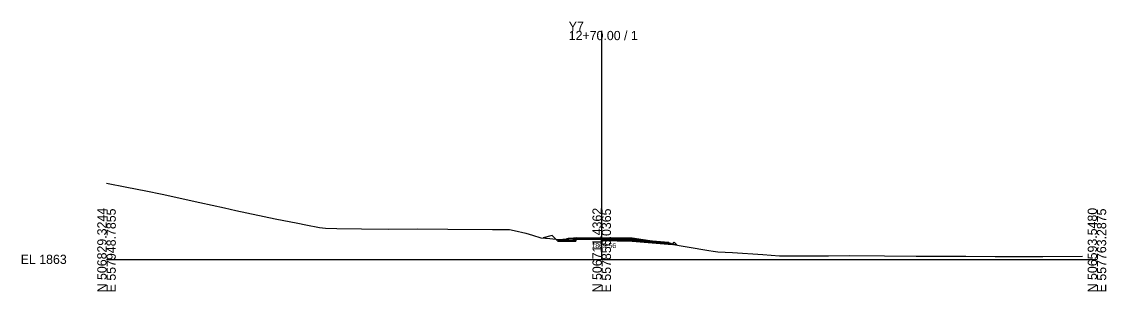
# Model space of a CAD drawing. Extents: x -26 to 557959, y -10 to 506992.
# Drawn here: x 1174.3 to 1502.8, y 490.3 to 572 of the extents above; entities that cross this region are included whole.
import ezdxf

# ---------------------------------------------------------------- set-up
doc = ezdxf.new("R2010")
doc.units = 0
for name, color, linetype in [('Exist CMT Pavement', 7, 'Continuous'), ('Exist Cross Section Cell', 7, 'Continuous'), ('Exist XS Ground Line', 7, 'Continuous'), ('Prop CMT Pvmt Course 1 CG', 7, 'Continuous'), ('Prop CMT Pvmt Course 2', 7, 'Continuous'), ('Prop CMT Pvmt Course 2 Wedge', 7, 'Continuous'), ('Prop CMT Pvmt Course 3', 7, 'Continuous'), ('Prop CMT Pvmt Course 3 Wedge', 7, 'Continuous'), ('Prop CMT Pvmt Wedge Surface 2', 7, 'Continuous'), ('Prop CMT Pvmt Wedge Surface 3', 7, 'Continuous'), ('Prop CMT Shld Paved Course 2', 7, 'Continuous'), ('Prop CMT Shld Paved Course 3', 7, 'Continuous'), ('Prop XS Ditch Standard Text', 7, 'Continuous'), ('Prop XS Earthwork Shape', 7, 'Continuous')]:
    doc.layers.add(name, color=color, linetype=linetype)

msp = doc.modelspace()

# ---------------------------------------------------------------- linework, layer by layer
at = {"layer": 'Exist CMT Pavement'}
for points in [[(1350, 506.38), (1342.11, 506.41)], [(1342.11, 506.41), (1346.05, 506.4)], [(1346.05, 506.4), (1350, 506.38)]]:
    msp.add_lwpolyline(points, dxfattribs=at)
at = {"layer": 'Exist Cross Section Cell'}
for p, q in [((1350, 500), (1350, 569.24)), ((1200, 500), (1350, 500)), ((1350, 500), (1500, 500))]:
    msp.add_line(p, q, dxfattribs=at)
at = {"layer": 'Exist XS Ground Line'}
msp.add_lwpolyline([(1200, 523.08), (1206.11, 521.85), (1211.88, 520.81), (1216.9, 519.77), (1228.25, 517.27), (1235.71, 515.63), (1239.22, 514.8), (1251.05, 512.33), (1257.99, 511.01), (1260.35, 510.5), (1264.53, 509.66), (1266.38, 509.48), (1269.79, 509.31), (1277.23, 509.23), (1285.29, 509.19), (1294.15, 509.2), (1303.43, 509.17), (1316.91, 509.05), (1322.02, 509.01), (1323.49, 508.7), (1327.03, 507.91), (1329.06, 507.29), (1331.54, 506.55), (1334.33, 506.3), (1337.12, 506.03), (1339.31, 506.26), (1342.3, 506.59), (1350, 506.56), (1350.84, 506.55), (1351.85, 506.52), (1359.22, 506.29), (1364.57, 505.59), (1369.93, 504.84), (1382.48, 502.68), (1383.76, 502.46), (1385.16, 502.3), (1389.59, 502.12), (1398.82, 501.45), (1403.8, 501.07), (1404.51, 501.07), (1418.66, 501.08), (1425.16, 501.14), (1435.65, 501.07), (1445.29, 500.99), (1460.25, 500.92), (1469.22, 500.9), (1483.58, 500.87), (1495.63, 500.93)], dxfattribs=at)
at = {"layer": 'Prop CMT Pvmt Course 1 CG'}
for points in [[(1341.5, 505.8), (1337, 505.8), (1336.7, 505.5)], [(1336.7, 505.5), (1341.5, 505.5)], [(1341.5, 505.5), (1341.5, 505.8)]]:
    msp.add_lwpolyline(points, dxfattribs=at)
at = {"layer": 'Prop CMT Pvmt Course 2'}
for points in [[(1342.11, 506.14), (1341.5, 506.13)], [(1341.5, 506.13), (1341.5, 505.88)], [(1342.11, 505.89), (1342.11, 506.14)], [(1350, 506.05), (1350, 506.3)], [(1350, 506.3), (1359.19, 506.12)], [(1359.19, 505.87), (1350, 506.05)], [(1341.5, 505.88), (1342.11, 505.89)], [(1367.99, 505.38), (1367.97, 505.13)]]:
    msp.add_lwpolyline(points, dxfattribs=at)
at = {"layer": 'Prop CMT Pvmt Course 2 Wedge'}
msp.add_lwpolyline([(1350, 506.3), (1342.11, 506.14)], dxfattribs=at)
at = {"layer": 'Prop CMT Pvmt Course 3'}
for points in [[(1350, 505.67), (1350, 506.05)], [(1350, 506.05), (1359.19, 505.87)], [(1342.11, 505.89), (1341.5, 505.88)], [(1341.5, 505.88), (1341.5, 505.5)], [(1341.5, 505.5), (1342.11, 505.52)], [(1342.11, 505.52), (1342.11, 505.89)], [(1359.19, 505.49), (1350, 505.67)], [(1367.97, 505.13), (1367.95, 504.75)]]:
    msp.add_lwpolyline(points, dxfattribs=at)
at = {"layer": 'Prop CMT Pvmt Course 3 Wedge'}
msp.add_lwpolyline([(1350, 506.05), (1342.11, 505.89)], dxfattribs=at)
at = {"layer": 'Prop CMT Pvmt Wedge Surface 2'}
for points in [[(1341.5, 506.13), (1341.5, 506.38)], [(1350, 506.3), (1341.5, 506.13)]]:
    msp.add_lwpolyline(points, dxfattribs=at)
at = {"layer": 'Prop CMT Pvmt Wedge Surface 3'}
for points in [[(1341.5, 505.88), (1341.5, 506.38)], [(1350, 506.05), (1341.5, 505.88)]]:
    msp.add_lwpolyline(points, dxfattribs=at)
at = {"layer": 'Prop CMT Shld Paved Course 2'}
for points in [[(1341.5, 506.13), (1341.5, 506.13), (1341.5, 505.88), (1341.5, 505.88)], [(1341.5, 505.88), (1341.5, 506.13)], [(1359.19, 506.12), (1370.24, 505.19), (1370.48, 504.92)], [(1370.48, 504.92), (1359.19, 505.86)], [(1367.97, 505.13), (1367.99, 505.38)]]:
    msp.add_lwpolyline(points, dxfattribs=at)
at = {"layer": 'Prop CMT Shld Paved Course 3'}
for points in [[(1341.5, 505.88), (1341.5, 505.88), (1341.5, 505.5), (1341.5, 505.5)], [(1341.5, 505.5), (1341.5, 505.88)], [(1359.19, 505.86), (1370.48, 504.92), (1370.98, 504.88), (1371.33, 504.47)], [(1371.33, 504.47), (1359.19, 505.49)], [(1367.95, 504.75), (1367.97, 505.13)]]:
    msp.add_lwpolyline(points, dxfattribs=at)
at = {"layer": 'Prop XS Earthwork Shape'}
for points in [[(1332.25, 506.49), (1334.33, 506.3), (1336.08, 506.13), (1335.03, 507.18)], [(1337.12, 506.03), (1339.31, 506.26), (1339.5, 506.3), (1339.83, 506.31), (1341.5, 506.38), (1342.12, 506.41), (1342.11, 505.52), (1341.5, 505.5), (1336.7, 505.5), (1336.08, 506.13)], [(1350, 506.55), (1342.12, 506.41), (1341.5, 506.38), (1339.83, 506.31), (1342.3, 506.59)], [(1350, 506.55), (1342.12, 506.41), (1346.05, 506.4), (1350, 506.38)], [(1351.85, 506.52), (1359.19, 506.37), (1350, 506.55), (1350.84, 506.55)], [(1359.19, 505.49), (1371.33, 504.47), (1371.44, 504.58), (1369.93, 504.84), (1364.57, 505.59), (1359.19, 506.37), (1350, 506.55), (1350, 506.38), (1350, 505.67)], [(1371.99, 505.17), (1372.82, 504.34), (1371.44, 504.58)]]:
    msp.add_lwpolyline(points, close=True, dxfattribs=at)

# ---------------------------------------------------------------- texts
at = {"layer": 'Exist Cross Section Cell'}
for s, p in [('Y7', (1340, 569.24)), ('12+70.00 / 1', (1340, 566.44)), ('EL 1863', (1174, 498.6))]:
    msp.add_text(s, height=2.8, dxfattribs=at).set_placement(p)
for s, p in [('N 506829.3244', (1200, 490)), ('E 557948.7855', (1202.8, 490)), ('N 506711.4362', (1350, 490)), ('E 557856.0365', (1352.8, 490)), ('N 506593.5480', (1500, 490)), ('E 557763.2875', (1502.8, 490))]:
    msp.add_text(s, height=2.8, rotation=90, dxfattribs=at).set_placement(p)
at = {"layer": 'Prop XS Ditch Standard Text'}
msp.add_text('1869.56', height=1.5, dxfattribs=at).set_placement((1346.88, 503.41))

doc.saveas('drawing.dxf')
